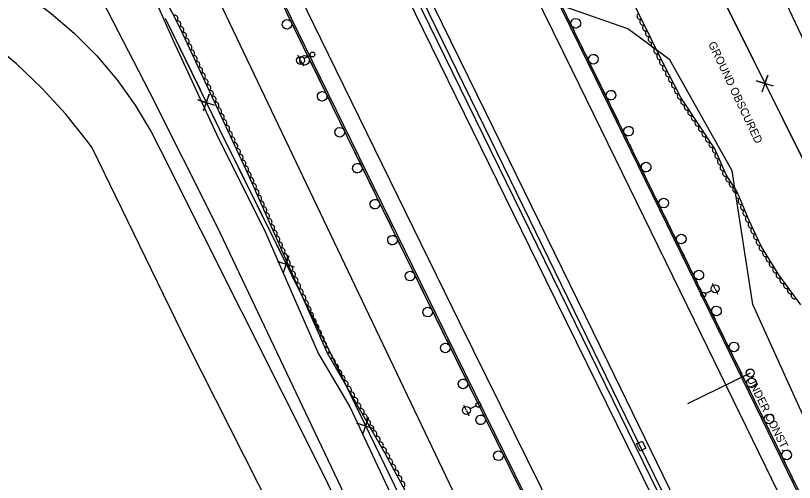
# Model space of a CAD drawing. Extents: x 1746719 to 1766531, y 631721 to 662391.
# Drawn here: x 1762829.8 to 1763316.5, y 635779.5 to 636071 of the extents above; entities that cross this region are included whole.
import ezdxf

# ---------------------------------------------------------------- set-up
doc = ezdxf.new("R2010")
doc.units = 0
for name, color, linetype in [('SURVEY - AERIAL SURVEY - Photo Control - Points - Elevations', 7, 'Continuous'), ('SURVEY - AERIAL SURVEY - Photo Control - Points - Locators', 7, 'Continuous'), ('SURVEY - AERIAL SURVEY - Photo Control - Points - Numbers', 7, 'Continuous'), ('SURVEY - AERIAL SURVEY - Photo Control with Text', 7, 'Continuous'), ('SURVEY - CENTERLINE - Existing Roads - Development', 7, 'Continuous'), ('SURVEY - CENTERLINE - Existing Roads Curve Text', 7, 'Continuous'), ('SURVEY - CENTERLINE - Preliminary Curve Text', 7, 'Continuous'), ('SURVEY - CONTROL - Points - Locators', 7, 'Continuous')]:
    doc.layers.add(name, color=color, linetype=linetype)

msp = doc.modelspace()

# ---------------------------------------------------------------- linework, layer by layer
at = {"layer": 'SURVEY - AERIAL SURVEY - Photo Control - Points - Elevations'}
for points in [[(1763704.89, 634983.66), (1763640.33, 635116.26), (1763572.67, 635254.52), (1763501.45, 635399.63), (1763427.19, 635551.31), (1763340.37, 635728.58), (1763263.89, 635885.41), (1763187.43, 636041.67), (1763122.68, 636173.79), (1763042.99, 636337.18), (1762975.48, 636475.16), (1762847.24, 636736.51)], [(1763695, 634978.85), (1763630.44, 635111.43), (1763562.79, 635249.68), (1763491.57, 635394.79), (1763417.31, 635546.47), (1763330.49, 635723.75), (1763254.01, 635880.59), (1763177.55, 636036.83), (1763112.8, 636168.96), (1763033.11, 636332.35), (1762965.6, 636470.32), (1762837.37, 636731.67)], [(1763641.05, 634952.58), (1763576.52, 635085.11), (1763508.91, 635223.28), (1763437.7, 635368.38), (1763363.42, 635520.08), (1763276.58, 635697.4), (1763200.09, 635854.25), (1763123.66, 636010.44), (1763058.89, 636142.6), (1762979.2, 636306.01), (1762911.72, 636443.92), (1762783.5, 636705.24)], [(1762773.06, 636698.72), (1762814.67, 636613.42), (1762883.84, 636472.89), (1762954.11, 636329.07), (1763023.11, 636188.11), (1763074.26, 636083.06), (1763161.07, 635905.77), (1763211.77, 635802.95), (1763267.45, 635689.5), (1763370.88, 635477.29), (1763451.14, 635313.44)], [(1762719.13, 636672.41), (1762760.79, 636587.02), (1762829.97, 636446.47), (1762900.21, 636302.71), (1762969.19, 636161.79), (1763020.34, 636056.74), (1763107.22, 635879.31), (1763157.93, 635776.46), (1763213.56, 635663.14), (1763316.97, 635450.95), (1763397.25, 635287.05)], [(1762709.25, 636667.59), (1762750.92, 636582.18), (1762820.1, 636441.63), (1762890.33, 636297.87), (1762959.31, 636156.96), (1763010.46, 636051.91), (1763097.34, 635874.45), (1763148.06, 635771.61), (1763203.67, 635658.31), (1763307.08, 635446.12), (1763387.38, 635282.21)], [(1763135.75, 635458.81), (1763071.54, 635600.61), (1762937.1, 635866.44), (1762877.65, 635988.32), (1762874.88, 635992.15), (1762861.18, 636009.45), (1762846.27, 636025.73), (1762830.25, 636040.9), (1762813.18, 636054.88), (1762795.17, 636067.6), (1762720.15, 636117.9), (1762715.68, 636121.48), (1762700.95, 636134.6), (1762687.32, 636148.86), (1762674.91, 636164.18), (1762663.78, 636180.45), (1762654, 636197.57), (1762651.08, 636203.49), (1762639.92, 636224.16), (1762627.49, 636244.06), (1762613.86, 636263.12), (1762599.11, 636281.23), (1762576.28, 636314.43), (1762557.07, 636346.83)], [(1762653.05, 636292.18), (1762660.8, 636270.32), (1762669.98, 636248.99), (1762679.85, 636229.52), (1762692.79, 636209.19), (1762707.03, 636189.76), (1762722.52, 636171.32), (1762731.97, 636161.2), (1762759.23, 636140.17), (1762787.33, 636120.36), (1762788.93, 636119.29), (1762851.78, 636072.4), (1762866.68, 636059.74), (1762880.5, 636045.91), (1762893.15, 636030.99), (1762904.53, 636015.09), (1762914.57, 635998.31), (1762920.21, 635987.3), (1763021.68, 635785.45), (1763162.71, 635494.4)]]:
    msp.add_lwpolyline(points, dxfattribs=at)
at = {"layer": 'SURVEY - AERIAL SURVEY - Photo Control - Points - Locators'}
for points in [[(1762855.72, 636761.66), (1762915.79, 636794.06), (1762948.96, 636813.36), (1762952.81, 636806.93), (1763013.9, 636685.45), (1763025.09, 636662.89), (1763070.4, 636555.62), (1763094.41, 636499.13), (1763123.77, 636445.46), (1763150.07, 636397.69), (1763162.17, 636366.06), (1763198.22, 636302.04), (1763238.5, 636231.32), (1763273.29, 636158.17), (1763313.15, 636074.51), (1763350.67, 635995.46), (1763380.26, 635934.07), (1763411.62, 635868.46), (1763466.91, 635754.2), (1763477.33, 635732.13), (1763497.46, 635693.59), (1763531.02, 635629.76), (1763548.12, 635593.75), (1763602.09, 635502.11)], [(1763204.15, 635422.43), (1763116.49, 635602.37), (1763062.75, 635714.91), (1763035.04, 635772.4), (1762997.24, 635851.96), (1762955.69, 635939.33), (1762913.53, 636023.45), (1762845.39, 636155.37), (1762784.04, 636274.28), (1762742.24, 636365.28), (1762694.9, 636468.77), (1762629.15, 636613.34), (1762624.36, 636623.35), (1762686.72, 636660.03)], [(1762848.83, 636297.5), (1762876.64, 636247.08), (1762866.05, 636243.32), (1762875.87, 636210.11), (1762884.77, 636186.9), (1762887.04, 636153.05), (1762890.08, 636134.45), (1762910.47, 636095.39), (1762928.17, 636055.34), (1762955.26, 635996.85), (1762985.88, 635935.59), (1763019.08, 635859.66), (1763038.76, 635826.6), (1763068.71, 635762.7), (1763113.6, 635677.31), (1763150.03, 635609.52), (1763170.12, 635598.05), (1763197.18, 635544.24), (1763216.04, 635492.82)], [(1763340.83, 635779.81), (1763290.46, 635890.46), (1763277.66, 635974.07), (1763238.69, 636043.25), (1763212.38, 636062.62), (1763159.34, 636081.53), (1763131.35, 636144.86), (1763171.16, 636150.6), (1763171.2, 636159.94), (1763163.08, 636172.6), (1763180.47, 636197.55), (1763175.7, 636213.07), (1763172.64, 636221.87), (1763160.05, 636258.51), (1763156.96, 636267.33), (1763137.27, 636282.28), (1763128.15, 636292.06)]]:
    msp.add_lwpolyline(points, dxfattribs=at)
at = {"layer": 'SURVEY - AERIAL SURVEY - Photo Control - Points - Numbers'}
for p, q in [((1763288.92, 635847.78), (1763249.77, 635828.61)), ((1763288.92, 635847.76), (1763288.92, 635847.76)), ((1763288.92, 635847.76), (1763288.92, 635847.76))]:
    msp.add_line(p, q, dxfattribs=at)
for points in [[(1763446.24, 635514.67), (1763428.09, 635551.75), (1763341.27, 635729.02), (1763264.79, 635885.85), (1763188.33, 636042.11), (1763123.58, 636174.23), (1763043.89, 636337.61), (1762976.38, 636475.6), (1762848.14, 636736.95)], [(1762780.33, 636702.09), (1762833.11, 636593.25), (1762910.17, 636436.51), (1763005.6, 636241.46), (1763118.37, 636010.26), (1763219.08, 635804.06), (1763329.74, 635578.22), (1763441.15, 635350.94), (1763538.42, 635152.66), (1763637.77, 634949.46)], [(1763635.49, 634947.88), (1763550.57, 635121.13), (1763412.96, 635402), (1763296.92, 635639.14), (1763179.78, 635878.6), (1763016.73, 636211.43), (1762900.31, 636449.87), (1762810.07, 636633.97), (1762777.65, 636700.23)], [(1762754.81, 636572), (1762819.2, 636441.19), (1762889.43, 636297.43), (1762958.41, 636156.52), (1763009.56, 636051.47), (1763096.45, 635874.01), (1763147.16, 635771.16), (1763186.04, 635691.97)], [(1763000.1, 636070.91), (1763004.12, 636062.64)], [(1763179.18, 636060.77), (1763175.13, 636069.03)], [(1763005.53, 636059.76), (1763007.58, 636055.54)], [(1763007.58, 636055.54), (1763009.56, 636051.47), (1763009.64, 636051.31)], [(1763182.66, 636053.67), (1763180.59, 636057.89)], [(1763184.73, 636049.45), (1763182.66, 636053.67)], [(1763011.05, 636048.44), (1763015.09, 636040.17)], [(1763190.18, 636038.32), (1763188.33, 636042.11), (1763186.13, 636046.58)], [(1763016.5, 636037.3), (1763018.57, 636033.08)], [(1763193.65, 636031.22), (1763191.59, 636035.44)], [(1763018.57, 636033.08), (1763020.63, 636028.86)], [(1763195.72, 636027), (1763193.65, 636031.22)], [(1763022.04, 636025.98), (1763026.09, 636017.72)], [(1763201.17, 636015.86), (1763197.12, 636024.13)], [(1763027.49, 636014.84), (1763029.56, 636010.62)], [(1763029.56, 636010.62), (1763031.63, 636006.4)], [(1763204.64, 636008.77), (1763202.58, 636012.99)], [(1763206.71, 636004.55), (1763204.64, 636008.77)], [(1763033.03, 636003.53), (1763037.08, 635995.27)], [(1763212.16, 635993.41), (1763208.11, 636001.67)], [(1763038.49, 635992.39), (1763040.55, 635988.17)], [(1763040.55, 635988.17), (1763042.62, 635983.95)], [(1763215.63, 635986.31), (1763213.56, 635990.53)], [(1763217.7, 635982.09), (1763215.63, 635986.31)], [(1763044.03, 635981.08), (1763048.07, 635972.81)], [(1763223.15, 635970.95), (1763219.1, 635979.21)], [(1763049.48, 635969.94), (1763051.55, 635965.72)], [(1763226.62, 635963.85), (1763224.55, 635968.08)], [(1763051.55, 635965.72), (1763053.61, 635961.5)], [(1763228.68, 635959.63), (1763226.62, 635963.85)], [(1763055.02, 635958.62), (1763059.07, 635950.36)], [(1763234.14, 635948.5), (1763230.09, 635956.76)], [(1763060.47, 635947.48), (1763062.54, 635943.26)], [(1763062.54, 635943.26), (1763064.61, 635939.04)], [(1763237.61, 635941.4), (1763235.54, 635945.62)], [(1763239.67, 635937.18), (1763237.61, 635941.4)], [(1763066.01, 635936.17), (1763070.06, 635927.91)], [(1763245.12, 635926.04), (1763241.08, 635934.3)], [(1763071.47, 635925.03), (1763073.53, 635920.81)], [(1763248.6, 635918.94), (1763246.53, 635923.17)], [(1763073.53, 635920.81), (1763075.6, 635916.59)], [(1763250.66, 635914.72), (1763248.6, 635918.94)], [(1763077.01, 635913.71), (1763081.05, 635905.45)], [(1763256.11, 635903.58), (1763252.07, 635911.85)], [(1763082.46, 635902.58), (1763084.53, 635898.36)], [(1763084.53, 635898.36), (1763086.59, 635894.14)], [(1763259.58, 635896.49), (1763257.52, 635900.71)], [(1763261.65, 635892.27), (1763259.58, 635896.49)], [(1763088, 635891.26), (1763092.05, 635883)], [(1763267.09, 635881.13), (1763264.79, 635885.85), (1763263.06, 635889.39)], [(1763093.45, 635880.12), (1763095.52, 635875.9)], [(1763095.52, 635875.9), (1763096.45, 635874.01), (1763097.59, 635871.69)], [(1763270.56, 635874.03), (1763268.5, 635878.25)], [(1763272.62, 635869.8), (1763270.56, 635874.03)], [(1763099.01, 635868.82), (1763103.08, 635860.57)], [(1763278.05, 635858.66), (1763274.02, 635866.92)], [(1763104.49, 635857.7), (1763106.57, 635853.48)], [(1763281.51, 635851.55), (1763279.45, 635855.78)], [(1763106.57, 635853.48), (1763108.65, 635849.26)], [(1763283.57, 635847.33), (1763281.51, 635851.55)], [(1763110.06, 635846.39), (1763114.13, 635838.14)], [(1763289.01, 635836.18), (1763284.98, 635844.45)], [(1763115.55, 635835.27), (1763117.63, 635831.06)], [(1763117.63, 635831.06), (1763119.71, 635826.84)], [(1763292.47, 635829.08), (1763290.41, 635833.31)], [(1763294.53, 635824.86), (1763292.47, 635829.08)], [(1763121.12, 635823.97), (1763125.19, 635815.72)], [(1763299.97, 635813.71), (1763295.93, 635821.98)], [(1763126.6, 635812.85), (1763128.68, 635808.64)], [(1763303.43, 635806.61), (1763301.37, 635810.84)], [(1763128.68, 635808.64), (1763130.76, 635804.42)], [(1763305.49, 635802.39), (1763303.43, 635806.61)], [(1763132.18, 635801.55), (1763136.25, 635793.3)], [(1763310.92, 635791.24), (1763306.89, 635799.51)], [(1763137.66, 635790.43), (1763139.74, 635786.21)], [(1763314.39, 635784.14), (1763312.33, 635788.37)], [(1763139.74, 635786.21), (1763141.82, 635782)], [(1763316.45, 635779.92), (1763314.39, 635784.14)]]:
    msp.add_lwpolyline(points, dxfattribs=at)
msp.add_circle((1763288.92, 635847.78), 2.5, dxfattribs=at)
msp.add_circle((1763288.92, 635847.78), 2.5, dxfattribs=at)
for centre, start, end in [((1763179.87, 636066.18), 319.3771, 319.3631), ((1762999.39, 636065.5), 139.23, 139.216), ((1763010.36, 636043.02), 139.3551, 139.3411), ((1763190.87, 636043.73), 319.3771, 319.3631), ((1763021.35, 636020.57), 139.3551, 139.3411), ((1763201.86, 636021.27), 319.3431, 319.3292), ((1763032.34, 635998.12), 139.3551, 139.3411), ((1763212.85, 635998.82), 319.3431, 319.3292), ((1763043.34, 635975.67), 139.3551, 139.3411), ((1763223.84, 635976.36), 319.3431, 319.3292), ((1763234.83, 635953.91), 319.3431, 319.3292), ((1763054.33, 635953.21), 139.3551, 139.3411), ((1763065.32, 635930.76), 139.3551, 139.3411), ((1763245.81, 635931.45), 319.3431, 319.3292), ((1763076.32, 635908.31), 139.3551, 139.3411), ((1763256.8, 635908.99), 319.3431, 319.3292), ((1763087.31, 635885.85), 139.3551, 139.3411), ((1763267.79, 635886.53), 319.2644, 319.2504), ((1763098.33, 635863.4), 139.5166, 139.5026), ((1763278.75, 635864.06), 319.2644, 319.2504), ((1763109.39, 635840.98), 139.5166, 139.5026), ((1763289.71, 635841.59), 319.2644, 319.2504), ((1763120.45, 635818.56), 139.5166, 139.5026), ((1763300.67, 635819.12), 319.2644, 319.2504), ((1763131.5, 635796.14), 139.5166, 139.5026), ((1763311.62, 635796.65), 319.2644, 319.2504)]:
    msp.add_arc(centre, 3, start, end, dxfattribs=at)
at = {"layer": 'SURVEY - AERIAL SURVEY - Photo Control with Text'}
for points in [[(1763320.53, 635890.36), (1763306.77, 635909.11), (1763295.71, 635927.01), (1763287.99, 635943.42), (1763280.76, 635960.9), (1763273.88, 635971.58), (1763266.85, 635987.75), (1763245.61, 636019.87), (1763234.6, 636040.81), (1763211.57, 636087.8), (1763203.55, 636106.48), (1763200.4, 636118.65), (1763198.86, 636142.42), (1763193.36, 636156.08), (1763186.61, 636173.15), (1763180.49, 636190.48), (1763173.16, 636204.48), (1763164.69, 636225.76), (1763158.88, 636244.41), (1763153.59, 636263.33), (1763131.16, 636283.47), (1763108.44, 636311.78)], [(1762856.61, 636295.22), (1762881.67, 636249.02), (1762872.94, 636235.27), (1762882.07, 636200.39), (1762893.62, 636164.11), (1762897.96, 636130.75), (1762932.63, 636062.87), (1762974.87, 635972.06), (1763024.57, 635860.31), (1763060.63, 635797.79), (1763084.04, 635754.29), (1763119.06, 635675.51), (1763154.39, 635610.69), (1763170.08, 635601.49), (1763174.25, 635596.03), (1763196.88, 635550.7), (1763215.92, 635502.93)]]:
    msp.add_lwpolyline(points, dxfattribs=at)
for centre, major_axis in [((1762929.37, 636069.25), (0.91, -1.78)), ((1763220.01, 636070.58), (-0.88, 1.8)), ((1763221.77, 636066.99), (-0.88, 1.8)), ((1762931.19, 636065.69), (0.91, -1.78)), ((1762932.99, 636062.12), (0.84, -1.81)), ((1763223.53, 636063.4), (-0.88, 1.8)), ((1762934.67, 636058.49), (0.84, -1.81)), ((1763225.29, 636059.81), (-0.88, 1.8)), ((1762936.36, 636054.86), (0.84, -1.81)), ((1763227.05, 636056.22), (-0.88, 1.8)), ((1763228.81, 636052.62), (-0.88, 1.8)), ((1762938.05, 636051.24), (0.84, -1.81)), ((1762939.73, 636047.61), (0.84, -1.81)), ((1763230.57, 636049.03), (-0.88, 1.8)), ((1762941.42, 636043.98), (0.84, -1.81)), ((1763232.33, 636045.44), (-0.88, 1.8)), ((1762943.11, 636040.35), (0.84, -1.81)), ((1763234.09, 636041.85), (-0.88, 1.8)), ((1763235.93, 636038.29), (-0.93, 1.77)), ((1762944.79, 636036.73), (0.84, -1.81)), ((1762946.48, 636033.1), (0.84, -1.81)), ((1763237.79, 636034.75), (-0.93, 1.77)), ((1762948.17, 636029.47), (0.84, -1.81)), ((1763239.65, 636031.21), (-0.93, 1.77)), ((1762949.85, 636025.85), (0.84, -1.81)), ((1763241.51, 636027.67), (-0.93, 1.77)), ((1763243.37, 636024.13), (-0.93, 1.77)), ((1762951.54, 636022.22), (0.84, -1.81)), ((1762953.23, 636018.59), (0.84, -1.81)), ((1763245.23, 636020.59), (-0.93, 1.77)), ((1762954.91, 636014.97), (0.84, -1.81)), ((1763247.37, 636017.21), (-1.1, 1.67)), ((1763249.57, 636013.88), (-1.1, 1.67)), ((1762956.6, 636011.34), (0.84, -1.81)), ((1763251.78, 636010.54), (-1.1, 1.67)), ((1762958.29, 636007.71), (0.84, -1.81)), ((1762959.97, 636004.09), (0.84, -1.81)), ((1763253.99, 636007.2), (-1.1, 1.67)), ((1763256.19, 636003.87), (-1.1, 1.67)), ((1762961.66, 636000.46), (0.84, -1.81)), ((1763258.4, 636000.53), (-1.1, 1.67)), ((1762963.35, 635996.83), (0.84, -1.81)), ((1763260.61, 635997.19), (-1.1, 1.67)), ((1762965.03, 635993.2), (0.84, -1.81)), ((1762966.72, 635989.58), (0.84, -1.81)), ((1763262.81, 635993.86), (-1.1, 1.67)), ((1763265.02, 635990.52), (-1.1, 1.67)), ((1762968.41, 635985.95), (0.84, -1.81)), ((1763267.12, 635987.13), (-0.8, 1.83)), ((1762970.09, 635982.32), (0.84, -1.81)), ((1763268.72, 635983.46), (-0.8, 1.83)), ((1763270.31, 635979.79), (-0.8, 1.83)), ((1762971.78, 635978.7), (0.84, -1.81)), ((1762973.47, 635975.07), (0.84, -1.81)), ((1763271.91, 635976.12), (-0.8, 1.83)), ((1762975.14, 635971.44), (0.81, -1.83)), ((1763273.5, 635972.46), (-0.8, 1.83)), ((1762976.77, 635967.78), (0.81, -1.83)), ((1763275.53, 635969.02), (-1.08, 1.68)), ((1763277.7, 635965.66), (-1.08, 1.68)), ((1762978.4, 635964.13), (0.81, -1.83)), ((1762980.02, 635960.47), (0.81, -1.83)), ((1763279.86, 635962.29), (-1.08, 1.68)), ((1762981.65, 635956.82), (0.81, -1.83)), ((1763281.65, 635958.73), (-0.76, 1.85)), ((1763283.18, 635955.04), (-0.76, 1.85)), ((1762983.27, 635953.16), (0.81, -1.83)), ((1763284.71, 635951.34), (-0.76, 1.85)), ((1762984.9, 635949.51), (0.81, -1.83)), ((1762986.52, 635945.85), (0.81, -1.83)), ((1763286.24, 635947.65), (-0.76, 1.85)), ((1762988.15, 635942.2), (0.81, -1.83)), ((1763287.77, 635943.95), (-0.76, 1.85)), ((1763289.45, 635940.32), (-0.85, 1.81)), ((1762989.77, 635938.54), (0.81, -1.83)), ((1763291.15, 635936.7), (-0.85, 1.81)), ((1762991.4, 635934.89), (0.81, -1.83)), ((1762993.02, 635931.23), (0.81, -1.83)), ((1763292.85, 635933.08), (-0.85, 1.81)), ((1762994.65, 635927.58), (0.81, -1.83)), ((1763294.56, 635929.46), (-0.85, 1.81)), ((1763296.39, 635925.91), (-1.05, 1.7)), ((1762996.27, 635923.92), (0.81, -1.83)), ((1763298.49, 635922.51), (-1.05, 1.7)), ((1762997.9, 635920.27), (0.81, -1.83)), ((1762999.53, 635916.61), (0.81, -1.83)), ((1763300.6, 635919.11), (-1.05, 1.7)), ((1763001.15, 635912.96), (0.81, -1.83)), ((1763302.7, 635915.7), (-1.05, 1.7)), ((1763304.8, 635912.3), (-1.05, 1.7)), ((1763002.78, 635909.31), (0.81, -1.83)), ((1763306.92, 635908.91), (-1.18, 1.61)), ((1763004.4, 635905.65), (0.81, -1.83)), ((1763006.03, 635902), (0.81, -1.83)), ((1763309.29, 635905.68), (-1.18, 1.61)), ((1763311.65, 635902.46), (-1.18, 1.61)), ((1763007.65, 635898.34), (0.81, -1.83)), ((1763314.02, 635899.24), (-1.18, 1.61)), ((1763009.28, 635894.69), (0.81, -1.83)), ((1763316.39, 635896.01), (-1.18, 1.61)), ((1763010.9, 635891.03), (0.81, -1.83)), ((1763012.53, 635887.38), (0.81, -1.83)), ((1763014.15, 635883.72), (0.81, -1.83)), ((1763015.78, 635880.07), (0.81, -1.83)), ((1763017.41, 635876.41), (0.81, -1.83)), ((1763019.03, 635872.76), (0.81, -1.83)), ((1763020.66, 635869.1), (0.81, -1.83)), ((1763022.28, 635865.45), (0.81, -1.83)), ((1763023.91, 635861.79), (0.81, -1.83)), ((1763025.75, 635858.25), (1, -1.73)), ((1763027.75, 635854.78), (1, -1.73)), ((1763029.75, 635851.32), (1, -1.73)), ((1763031.75, 635847.85), (1, -1.73)), ((1763033.75, 635844.39), (1, -1.73)), ((1763035.75, 635840.93), (1, -1.73)), ((1763037.75, 635837.46), (1, -1.73)), ((1763039.74, 635834), (1, -1.73)), ((1763041.74, 635830.53), (1, -1.73)), ((1763043.74, 635827.07), (1, -1.73)), ((1763045.74, 635823.6), (1, -1.73)), ((1763047.74, 635820.14), (1, -1.73)), ((1763049.74, 635816.67), (1, -1.73)), ((1763051.74, 635813.21), (1, -1.73)), ((1763053.73, 635809.74), (1, -1.73)), ((1763055.73, 635806.28), (1, -1.73)), ((1763057.73, 635802.81), (1, -1.73)), ((1763059.73, 635799.35), (1, -1.73)), ((1763061.67, 635795.85), (0.95, -1.76)), ((1763063.57, 635792.33), (0.95, -1.76)), ((1763065.46, 635788.81), (0.95, -1.76)), ((1763067.36, 635785.28), (0.95, -1.76)), ((1763069.25, 635781.76), (0.95, -1.76)), ((1763071.15, 635778.24), (0.95, -1.76))]:
    msp.add_ellipse(centre, major_axis=major_axis, ratio=0.940188, start_param=0, end_param=3.141593, dxfattribs=at)
at = {"layer": 'SURVEY - CENTERLINE - Existing Roads - Development'}
for p, q in [((1763007.92, 636042.99), (1763006.24, 636046.34)), ((1763013.96, 636046.02), (1763010.16, 636044.11)), ((1763007.92, 636042.99), (1763009.61, 636039.64)), ((1763266.91, 635900.43), (1763265.22, 635903.78)), ((1763260.89, 635897.39), (1763264.68, 635899.3)), ((1763266.91, 635900.43), (1763268.6, 635897.08)), ((1763111.53, 635824.41), (1763109.92, 635827.8)), ((1763117.63, 635827.3), (1763113.79, 635825.48)), ((1763111.53, 635824.41), (1763113.13, 635821.02))]:
    msp.add_line(p, q, dxfattribs=at)
for centre, radius in [((1763007.92, 636042.99), 2.5), ((1763015.3, 636046.7), 1.5), ((1763266.91, 635900.43), 2.5), ((1763259.55, 635896.71), 1.5), ((1763111.53, 635824.41), 2.5), ((1763118.99, 635827.94), 1.5)]:
    msp.add_circle(centre, radius, dxfattribs=at)
at = {"layer": 'SURVEY - CENTERLINE - Existing Roads Curve Text'}
for points in [[(1762928.82, 636789.81), (1762960.97, 636723.74), (1763086.1, 636454.87), (1763365.02, 635894.2), (1763461.56, 635698.81)], [(1763272.04, 636081.1), (1763294.31, 636036.34)], [(1762923.24, 636069.27), (1762957.11, 636000.16), (1763028.37, 635856.25), (1763111.26, 635685.64), (1763194.35, 635513.86), (1763262.7, 635375.98), (1763309.84, 635279.41), (1763375.45, 635145.07), (1763450.62, 634988.03), (1763508.77, 634868.73)], [(1762923.24, 636069.27), (1762945.24, 636024.37)], [(1763303.41, 636026.8), (1763292.73, 636030.31), (1763298.09, 636028.51), (1763299.89, 636033.87), (1763296.25, 636023.23)], [(1762954.29, 636014.77), (1762943.63, 636018.35), (1762948.98, 636016.52), (1762950.81, 636021.87), (1762947.11, 636011.25)], [(1763301.48, 636021.92), (1763322.14, 635980.38)], [(1762952.33, 636009.92), (1762957.11, 636000.16), (1762972.88, 635968.31)], [(1762972.88, 635968.31), (1762995.07, 635923.51)], [(1763004.15, 635913.95), (1762993.48, 635917.47), (1762998.84, 635915.67), (1763000.65, 635921.03), (1762996.98, 635910.4)], [(1763002.21, 635909.08), (1763022.8, 635867.5)], [(1763022.8, 635867.5), (1763028.37, 635856.25), (1763044.74, 635822.57)], [(1763053.75, 635812.94), (1763043.1, 635816.55), (1763048.45, 635814.7), (1763050.3, 635820.04), (1763046.55, 635809.44)], [(1763051.77, 635808.08), (1763072.05, 635766.35)]]:
    msp.add_lwpolyline(points, dxfattribs=at)
at = {"layer": 'SURVEY - CENTERLINE - Preliminary Curve Text'}
msp.add_line((1763220.79, 635802.15), (1763220.79, 635802.15), dxfattribs=at)
msp.add_lwpolyline([(1763217.87, 635803.47), (1763221.44, 635805.28), (1763223.71, 635800.83), (1763220.14, 635799.01), (1763217.87, 635803.47)], dxfattribs=at)
at = {"layer": 'SURVEY - CONTROL - Points - Locators'}
msp.add_lwpolyline([(1762882.93, 636235.43), (1763301.15, 635359.33), (1763310.01, 635338.15), (1763312.56, 635307.31), (1763308.38, 635285.24), (1763243.49, 635159.25)], dxfattribs=at)

# ---------------------------------------------------------------- texts
at = {"layer": 'SURVEY - AERIAL SURVEY - Photo Control - Points - Locators'}
for s, rotation, p in [('GROUND OBSCURED', 295.4469, (1763262.51, 636053.3)), ('UNDER CONST.', 296.291, (1763286.61, 635844.17))]:
    msp.add_text(s, height=5, rotation=rotation, dxfattribs=at).set_placement(p)

doc.saveas('drawing.dxf')
